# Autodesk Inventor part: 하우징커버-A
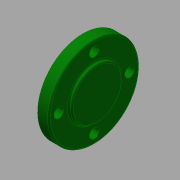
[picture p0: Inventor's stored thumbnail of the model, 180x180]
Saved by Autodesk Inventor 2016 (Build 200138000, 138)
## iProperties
Created: 2018-01
Part Number: 하우징커버-A
Material: 알루미늄 6061
Document SubType Name: Modeling
Designer: mduedu
Density: 2.71 g/cm^3
Appearance: 진녹색
Mass: 8.99967 g
Surface Area: 21.1948 cm^2
Volume: 3.32091 cm^3
Author: mduedu
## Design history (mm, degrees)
sketch "스케치1"
  geometry: C1 r 16 at (0, 0); 1 further point
  constraints: 1 centre point, 1 coincident
  dimensions: "d0" = 32 diameter of C1
extrude "돌출1" new body sketch "스케치1" distance "d1" = 4; taper "d2" = 0 deg
sketch "스케치2"
  geometry: C1 r 9 at (0, 0); 1 further point
  constraints: 1 centre point, 1 coincident
  dimensions: "d3" = 18 diameter of C1
extrude "돌출2" join sketch "스케치2" distance "d4" = 1; taper "d5" = 0 deg
fillet "모깎기1" dims "d6" = 0.5
fillet "모깎기2" dims "d7" = 0.5
sketch "스케치3" dims "d8" = 25
  geometry: 6 further points
  constraints: 2 vertical alignment, 1 coincident, 7 other
  dimensions: "d11" = 360 deg dimension on point (0, 0) point (0, 12.5) (derived)
sketch "스케치4"
  geometry: 4 further points
  constraints: 4 other
hole "구멍1" sketch "스케치4" at (-12.5, 0), (0, -12.5), (12.5, 0), (0, 12.5) diameter "d13" = 3.4; stored, may be unused: countersink angle "d17" = 90 deg, drill point angle "d19" = 0 deg; dims "d14" = 6, "d15" = 4, "d16" = 2, "d18" = 8
node "솔리드1"
